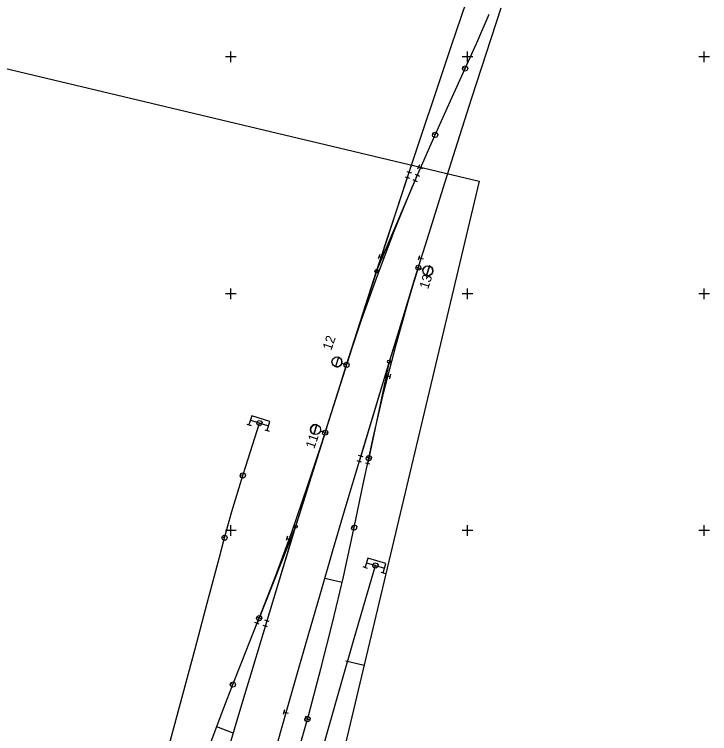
# Model space of a CAD drawing. Extents: x -733601 to -733291, y -1137892 to -1137187.
# Drawn here: x -733445.8 to -733298.9, y -1137492.9 to -1137341 of the extents above; entities that cross this region are included whole.
import ezdxf

# ---------------------------------------------------------------- set-up
doc = ezdxf.new("R2010")
doc.units = 0
for name, color, linetype in [('Krizky_Hektom_sit', 7, 'Continuous'), ('Rozvrzeni', 7, 'Continuous'), ('SIT_PUV_ZELEZNICE', 7, 'Continuous')]:
    doc.layers.add(name, color=color, linetype=linetype)

msp = doc.modelspace()

# ---------------------------------------------------------------- linework, layer by layer
at = {"layer": 'Krizky_Hektom_sit'}
for p, q in [((-733400, -1137351.13), (-733400, -1137348.87)), ((-733350, -1137351.13), (-733350, -1137348.87)), ((-733300, -1137351.13), (-733300, -1137348.87)), ((-733398.87, -1137350), (-733401.13, -1137350)), ((-733348.87, -1137350), (-733351.13, -1137350)), ((-733298.87, -1137350), (-733301.13, -1137350)), ((-733400, -1137401.13), (-733400, -1137398.87)), ((-733350, -1137401.13), (-733350, -1137398.87)), ((-733300, -1137401.13), (-733300, -1137398.87)), ((-733398.87, -1137400), (-733401.13, -1137400)), ((-733348.87, -1137400), (-733351.13, -1137400)), ((-733298.87, -1137400), (-733301.13, -1137400)), ((-733400, -1137451.13), (-733400, -1137448.87)), ((-733350, -1137451.13), (-733350, -1137448.87)), ((-733300, -1137451.13), (-733300, -1137448.87)), ((-733398.87, -1137450), (-733401.13, -1137450)), ((-733348.87, -1137450), (-733351.13, -1137450)), ((-733298.87, -1137450), (-733301.13, -1137450))]:
    msp.add_line(p, q, dxfattribs=at)
at = {"layer": 'Rozvrzeni'}
msp.add_line((-733375.74, -1137477.48), (-733371.85, -1137478.4), dxfattribs=at)
msp.add_lwpolyline([(-733564.93, -1137648.32), (-733492.01, -1137341.87), (-733347.54, -1137376.25), (-733420.47, -1137682.7)], close=True, dxfattribs=at)
at = {"layer": 'SIT_PUV_ZELEZNICE'}
for p, q in [((-733350.98, -1137352.24), (-733350.87, -1137352.01)), ((-733350.87, -1137352.01), (-733350.54, -1137351.88)), ((-733350.54, -1137351.88), (-733350.09, -1137352.09)), ((-733351.08, -1137352.46), (-733350.98, -1137352.24)), ((-733350.95, -1137352.79), (-733351.08, -1137352.46)), ((-733350.52, -1137352.44), (-733350.98, -1137352.24)), ((-733350.5, -1137353), (-733350.95, -1137352.79)), ((-733350.17, -1137352.88), (-733350.5, -1137353)), ((-733349.96, -1137352.42), (-733350.17, -1137352.88)), ((-733350.09, -1137352.09), (-733349.96, -1137352.42)), ((-733357.44, -1137366.49), (-733357.34, -1137366.26)), ((-733357.32, -1137366.82), (-733357.44, -1137366.49)), ((-733357.34, -1137366.26), (-733357.24, -1137366.03)), ((-733356.89, -1137366.47), (-733357.34, -1137366.26)), ((-733356.86, -1137367.03), (-733357.32, -1137366.82)), ((-733357.24, -1137366.03), (-733356.91, -1137365.91)), ((-733356.91, -1137365.91), (-733356.45, -1137366.12)), ((-733356.53, -1137366.9), (-733356.86, -1137367.03)), ((-733356.33, -1137366.45), (-733356.53, -1137366.9)), ((-733356.45, -1137366.12), (-733356.33, -1137366.45)), ((-733360.19, -1137372.76), (-733360.6, -1137373.67)), ((-733359.48, -1137373.62), (-733360.4, -1137373.21)), ((-733368.56, -1137391.68), (-733368.89, -1137392.62)), ((-733367.78, -1137392.48), (-733368.73, -1137392.15)), ((-733360.15, -1137391.96), (-733360.45, -1137392.91)), ((-733359.35, -1137392.73), (-733360.3, -1137392.44)), ((-733360.97, -1137394.58), (-733360.9, -1137394.35)), ((-733360.81, -1137394.9), (-733360.97, -1137394.58)), ((-733360.9, -1137394.35), (-733360.82, -1137394.11)), ((-733360.42, -1137394.49), (-733360.9, -1137394.35)), ((-733360.82, -1137394.11), (-733360.51, -1137393.94)), ((-733360.51, -1137393.94), (-733360.03, -1137394.09)), ((-733360.42, -1137394.49), (-733359.39, -1137394.83)), ((-733360.03, -1137394.09), (-733359.87, -1137394.4)), ((-733359.87, -1137394.4), (-733360.02, -1137394.88)), ((-733358.68, -1137396.15), (-733358.09, -1137394.14)), ((-733360.33, -1137395.05), (-733360.81, -1137394.9)), ((-733360.02, -1137394.88), (-733360.33, -1137395.05)), ((-733377.29, -1137413.38), (-733377.93, -1137415.39)), ((-733375.58, -1137415.02), (-733376.61, -1137414.7)), ((-733376.13, -1137415.11), (-733376.05, -1137414.87)), ((-733376.13, -1137415.11), (-733376.05, -1137414.87)), ((-733375.97, -1137415.42), (-733376.13, -1137415.11)), ((-733375.97, -1137415.42), (-733376.13, -1137415.11)), ((-733376.05, -1137414.87), (-733375.98, -1137414.63)), ((-733376.05, -1137414.87), (-733375.98, -1137414.63)), ((-733375.58, -1137415.02), (-733376.05, -1137414.87)), ((-733375.58, -1137415.02), (-733376.05, -1137414.87)), ((-733375.98, -1137414.63), (-733375.66, -1137414.47)), ((-733375.98, -1137414.63), (-733375.66, -1137414.47)), ((-733375.49, -1137415.57), (-733375.97, -1137415.42)), ((-733375.49, -1137415.57), (-733375.97, -1137415.42)), ((-733375.66, -1137414.47), (-733375.19, -1137414.62)), ((-733375.66, -1137414.47), (-733375.19, -1137414.62)), ((-733375.17, -1137415.41), (-733375.49, -1137415.57)), ((-733375.17, -1137415.41), (-733375.49, -1137415.57)), ((-733375.19, -1137414.62), (-733375.02, -1137414.93)), ((-733375.19, -1137414.62), (-733375.02, -1137414.93)), ((-733375.02, -1137414.93), (-733375.17, -1137415.41)), ((-733375.02, -1137414.93), (-733375.17, -1137415.41)), ((-733367.31, -1137417.23), (-733366.34, -1137417.46)), ((-733366.45, -1137417.95), (-733366.22, -1137416.97)), ((-733395.59, -1137425.75), (-733396.2, -1137427.66)), ((-733395.59, -1137425.75), (-733396.2, -1137427.66)), ((-733391.78, -1137426.96), (-733395.59, -1137425.75)), ((-733391.78, -1137426.96), (-733395.59, -1137425.75)), ((-733396.67, -1137427.51), (-733395.72, -1137427.81)), ((-733396.67, -1137427.51), (-733395.72, -1137427.81)), ((-733395.89, -1137426.7), (-733392.08, -1137427.91)), ((-733395.89, -1137426.7), (-733392.08, -1137427.91)), ((-733394.54, -1137427.4), (-733394.46, -1137427.16)), ((-733394.38, -1137427.71), (-733394.54, -1137427.4)), ((-733394.46, -1137427.16), (-733394.39, -1137426.92)), ((-733393.99, -1137427.31), (-733394.46, -1137427.16)), ((-733394.39, -1137426.92), (-733394.07, -1137426.76)), ((-733393.9, -1137427.86), (-733394.38, -1137427.71)), ((-733394.07, -1137426.76), (-733393.6, -1137426.91)), ((-733393.59, -1137427.7), (-733393.9, -1137427.86)), ((-733393.6, -1137426.91), (-733393.43, -1137427.22)), ((-733393.43, -1137427.22), (-733393.59, -1137427.7)), ((-733392.38, -1137428.87), (-733391.78, -1137426.96)), ((-733392.38, -1137428.87), (-733391.78, -1137426.96)), ((-733381.83, -1137427.68), (-733382.46, -1137429.68)), ((-733392.86, -1137428.72), (-733391.91, -1137429.02)), ((-733392.86, -1137428.72), (-733391.91, -1137429.02)), ((-733380.11, -1137429.32), (-733381.14, -1137428.99)), ((-733380.66, -1137429.41), (-733380.51, -1137428.93)), ((-733380.66, -1137429.41), (-733380.59, -1137429.17)), ((-733380.5, -1137429.72), (-733380.66, -1137429.41)), ((-733380.5, -1137429.72), (-733380.66, -1137429.41)), ((-733380.59, -1137429.17), (-733380.51, -1137428.93)), ((-733380.11, -1137429.32), (-733380.59, -1137429.17)), ((-733380.51, -1137428.93), (-733380.2, -1137428.77)), ((-733380.51, -1137428.93), (-733380.2, -1137428.77)), ((-733380.2, -1137428.77), (-733379.72, -1137428.92)), ((-733380.2, -1137428.77), (-733379.72, -1137428.92)), ((-733380.11, -1137429.32), (-733379.63, -1137429.47)), ((-733379.72, -1137428.92), (-733379.56, -1137429.23)), ((-733379.72, -1137428.92), (-733379.56, -1137429.23)), ((-733379.56, -1137429.23), (-733379.71, -1137429.71)), ((-733379.63, -1137429.47), (-733379.71, -1137429.71)), ((-733379.56, -1137429.23), (-733379.63, -1137429.47)), ((-733380.02, -1137429.87), (-733380.5, -1137429.72)), ((-733380.02, -1137429.87), (-733380.5, -1137429.72)), ((-733379.71, -1137429.71), (-733380.02, -1137429.87)), ((-733379.71, -1137429.71), (-733380.02, -1137429.87)), ((-733371.42, -1137434.85), (-733371.36, -1137434.6)), ((-733371.22, -1137435.14), (-733371.42, -1137434.85)), ((-733371.36, -1137434.6), (-733371.31, -1137434.36)), ((-733370.88, -1137434.71), (-733371.36, -1137434.6)), ((-733371.31, -1137434.36), (-733371.02, -1137434.17)), ((-733370.73, -1137435.25), (-733371.22, -1137435.14)), ((-733371.02, -1137434.17), (-733370.53, -1137434.27)), ((-733370.44, -1137435.05), (-733370.73, -1137435.25)), ((-733370.53, -1137434.27), (-733370.33, -1137434.56)), ((-733370.33, -1137434.56), (-733370.44, -1137435.05)), ((-733398.05, -1137438.46), (-733397.97, -1137438.22)), ((-733397.88, -1137438.77), (-733398.05, -1137438.46)), ((-733397.97, -1137438.22), (-733397.89, -1137437.98)), ((-733397.49, -1137438.37), (-733397.97, -1137438.22)), ((-733397.89, -1137437.98), (-733397.58, -1137437.82)), ((-733397.58, -1137437.82), (-733397.1, -1137437.97)), ((-733397.1, -1137437.97), (-733396.94, -1137438.28)), ((-733396.94, -1137438.28), (-733397.09, -1137438.76)), ((-733397.41, -1137438.92), (-733397.88, -1137438.77)), ((-733397.09, -1137438.76), (-733397.41, -1137438.92)), ((-733374.46, -1137449.28), (-733374.41, -1137449.04)), ((-733374.41, -1137449.04), (-733374.11, -1137448.84)), ((-733374.11, -1137448.84), (-733373.62, -1137448.95)), ((-733373.62, -1137448.95), (-733373.43, -1137449.24)), ((-733373.43, -1137449.24), (-733373.53, -1137449.73)), ((-733374.51, -1137449.53), (-733374.46, -1137449.28)), ((-733374.32, -1137449.82), (-733374.51, -1137449.53)), ((-733373.97, -1137449.38), (-733374.46, -1137449.28)), ((-733373.83, -1137449.92), (-733374.32, -1137449.82)), ((-733373.53, -1137449.73), (-733373.83, -1137449.92)), ((-733401.89, -1137451.66), (-733401.83, -1137451.42)), ((-733401.71, -1137451.97), (-733401.89, -1137451.66)), ((-733401.83, -1137451.42), (-733401.76, -1137451.18)), ((-733401.34, -1137451.55), (-733401.83, -1137451.42)), ((-733401.76, -1137451.18), (-733401.45, -1137451)), ((-733401.23, -1137452.1), (-733401.71, -1137451.97)), ((-733401.45, -1137451), (-733400.97, -1137451.13)), ((-733400.92, -1137451.92), (-733401.23, -1137452.1)), ((-733400.97, -1137451.13), (-733400.79, -1137451.44)), ((-733400.79, -1137451.44), (-733400.92, -1137451.92)), ((-733388.04, -1137451.18), (-733388.37, -1137452.13)), ((-733387.26, -1137451.98), (-733388.21, -1137451.65)), ((-733371.12, -1137455.85), (-733371.68, -1137457.76)), ((-733371.12, -1137455.85), (-733371.68, -1137457.76)), ((-733371.4, -1137456.8), (-733367.57, -1137457.94)), ((-733371.4, -1137456.8), (-733367.57, -1137457.94)), ((-733367.28, -1137456.98), (-733371.12, -1137455.85)), ((-733367.28, -1137456.98), (-733371.12, -1137455.85)), ((-733369.89, -1137456.99), (-733369.58, -1137456.82)), ((-733369.58, -1137456.82), (-733369.1, -1137456.96)), ((-733372.16, -1137457.62), (-733371.21, -1137457.91)), ((-733372.16, -1137457.62), (-733371.21, -1137457.91)), ((-733370.03, -1137457.47), (-733369.96, -1137457.23)), ((-733369.87, -1137457.78), (-733370.03, -1137457.47)), ((-733369.96, -1137457.23), (-733369.89, -1137456.99)), ((-733369.48, -1137457.37), (-733369.96, -1137457.23)), ((-733369.39, -1137457.92), (-733369.87, -1137457.78)), ((-733369.07, -1137457.76), (-733369.39, -1137457.92)), ((-733369.1, -1137456.96), (-733368.93, -1137457.28)), ((-733368.93, -1137457.28), (-733369.07, -1137457.76)), ((-733367.85, -1137458.9), (-733367.28, -1137456.98)), ((-733367.85, -1137458.9), (-733367.28, -1137456.98)), ((-733368.33, -1137458.76), (-733367.37, -1137459.04)), ((-733368.33, -1137458.76), (-733367.37, -1137459.04)), ((-733380.16, -1137460.02), (-733376.51, -1137460.88)), ((-733394.59, -1137468.53), (-733394.49, -1137468.3)), ((-733394.45, -1137468.86), (-733394.59, -1137468.53)), ((-733394.49, -1137468.3), (-733394.4, -1137468.07)), ((-733394.03, -1137468.48), (-733394.49, -1137468.3)), ((-733393.98, -1137469.04), (-733394.45, -1137468.86)), ((-733394.4, -1137468.07), (-733394.08, -1137467.93)), ((-733394.08, -1137467.93), (-733393.61, -1137468.11)), ((-733393.66, -1137468.9), (-733393.98, -1137469.04)), ((-733393.47, -1137468.44), (-733393.66, -1137468.9)), ((-733393.61, -1137468.11), (-733393.47, -1137468.44)), ((-733400.15, -1137482.54), (-733400.05, -1137482.31)), ((-733400.01, -1137482.86), (-733400.15, -1137482.54)), ((-733400.05, -1137482.31), (-733399.96, -1137482.07)), ((-733399.59, -1137482.49), (-733400.05, -1137482.31)), ((-733399.96, -1137482.07), (-733399.64, -1137481.93)), ((-733399.64, -1137481.93), (-733399.17, -1137482.12)), ((-733399.03, -1137482.44), (-733399.22, -1137482.91)), ((-733399.17, -1137482.12), (-733399.03, -1137482.44)), ((-733399.54, -1137483.05), (-733400.01, -1137482.86)), ((-733399.22, -1137482.91), (-733399.54, -1137483.05)), ((-733388.7, -1137487.88), (-733388.98, -1137488.84)), ((-733387.88, -1137488.64), (-733388.84, -1137488.36)), ((-733384.19, -1137489.2), (-733384.47, -1137490.16)), ((-733384.4, -1137489.93), (-733384.33, -1137489.69)), ((-733384.22, -1137490.24), (-733384.4, -1137489.93)), ((-733384.33, -1137489.69), (-733384.26, -1137489.45)), ((-733383.37, -1137489.96), (-733384.33, -1137489.68)), ((-733383.85, -1137489.82), (-733384.33, -1137489.69)), ((-733384.26, -1137489.45), (-733383.96, -1137489.27)), ((-733383.74, -1137490.37), (-733384.22, -1137490.24)), ((-733383.96, -1137489.27), (-733383.47, -1137489.41)), ((-733383.43, -1137490.2), (-733383.74, -1137490.37)), ((-733383.47, -1137489.41), (-733383.3, -1137489.71)), ((-733383.3, -1137489.71), (-733383.43, -1137490.2)), ((-733399.51, -1137492.76), (-733403.02, -1137491.43))]:
    msp.add_line(p, q, dxfattribs=at)
for points in [[(-733401.75, -1137500.31), (-733398.91, -1137490.72), (-733396.88, -1137483.92), (-733396.05, -1137481.14), (-733393.16, -1137471.57), (-733390.25, -1137462), (-733387.32, -1137452.44), (-733384.36, -1137442.89), (-733381.37, -1137433.34), (-733378.37, -1137423.81), (-733375.34, -1137414.28), (-733372.28, -1137404.75), (-733369.21, -1137395.24), (-733366.11, -1137385.73), (-733362.98, -1137376.23), (-733359.83, -1137366.74), (-733356.66, -1137357.26), (-733353.46, -1137347.78), (-733350.24, -1137338.32)], [(-733392.24, -1137502.27), (-733389.54, -1137492.65), (-733387.78, -1137486.44), (-733386.8, -1137483.03), (-733384.05, -1137473.42), (-733381.26, -1137463.81), (-733378.46, -1137454.21), (-733375.63, -1137444.62), (-733372.78, -1137435.04), (-733369.9, -1137425.46), (-733367, -1137415.89), (-733364.07, -1137406.33), (-733361.13, -1137396.77), (-733358.15, -1137387.22), (-733355.16, -1137377.68), (-733352.14, -1137368.15), (-733349.09, -1137358.63), (-733346.02, -1137349.11), (-733342.93, -1137339.6)], [(-733375.58, -1137415.02), (-733372.43, -1137405.53), (-733369.07, -1137396.11), (-733365.5, -1137386.77), (-733361.72, -1137377.51), (-733357.73, -1137368.34), (-733357.03, -1137366.79), (-733356.92, -1137366.55), (-733356.89, -1137366.47), (-733356.81, -1137366.31), (-733353.6, -1137359.23), (-733350.52, -1137352.44), (-733349.47, -1137350.12), (-733348.16, -1137347.17), (-733348.01, -1137346.84), (-733347.87, -1137346.51), (-733345.46, -1137340.96)], [(-733362.82, -1137374.16), (-733361.87, -1137374.48)], [(-733362.72, -1137375.46), (-733362.41, -1137374.51), (-733362.35, -1137374.32)], [(-733361.1, -1137374.77), (-733360.18, -1137375.16)], [(-733375.58, -1137415.02), (-733369.25, -1137395.21), (-733362.72, -1137375.46)], [(-733369.25, -1137395.21), (-733361.11, -1137376.07)], [(-733363.2, -1137375.3), (-733362.25, -1137375.62)], [(-733361.57, -1137375.88), (-733360.65, -1137376.27)], [(-733361.11, -1137376.07), (-733360.71, -1137375.15), (-733360.64, -1137374.97)], [(-733386.27, -1137498.5), (-733383.85, -1137489.82), (-733383.58, -1137488.87), (-733380.99, -1137479.21), (-733378.54, -1137469.51), (-733376.25, -1137459.78), (-733374.1, -1137450.01), (-733373.97, -1137449.38), (-733372.04, -1137440.23), (-733370.88, -1137434.71), (-733369.96, -1137430.45), (-733367.69, -1137420.71), (-733365.2, -1137411.02), (-733362.5, -1137401.39), (-733360.42, -1137394.49)], [(-733360.42, -1137394.49), (-733366.59, -1137414.36), (-733372.55, -1137434.28)], [(-733358.09, -1137394.14), (-733358.68, -1137396.15)], [(-733377.29, -1137413.38), (-733377.93, -1137415.39)], [(-733380.11, -1137429.32), (-733377.37, -1137420.65), (-733375.58, -1137415.02)], [(-733366.59, -1137414.36), (-733370.87, -1137434.71)], [(-733432.61, -1137592.18), (-733430.24, -1137582.46), (-733428.19, -1137572.68), (-733426.48, -1137562.82), (-733425.1, -1137553.05), (-733425.09, -1137552.92), (-733424.53, -1137548.39), (-733423.8, -1137543), (-733422.2, -1137533.13), (-733420.24, -1137523.33), (-733417.92, -1137513.6), (-733417.28, -1137511.16), (-733415.35, -1137503.94), (-733412.77, -1137494.28), (-733410.18, -1137484.62), (-733407.6, -1137474.96), (-733405.02, -1137465.3), (-733402.43, -1137455.64), (-733401.34, -1137451.55), (-733399.8, -1137445.99), (-733397.49, -1137438.37), (-733396.88, -1137436.43), (-733393.99, -1137427.31)], [(-733382.46, -1137429.68), (-733381.83, -1137427.68)], [(-733424.19, -1137560.03), (-733423.14, -1137555.99), (-733422.64, -1137554.1), (-733420.03, -1137544.45), (-733419.6, -1137542.91), (-733417.3, -1137534.83), (-733414.46, -1137525.24), (-733413.69, -1137522.71), (-733413.65, -1137522.55), (-733411.49, -1137515.69), (-733408.35, -1137506.2), (-733407.14, -1137502.71), (-733405.02, -1137496.77), (-733401.51, -1137487.4), (-733399.59, -1137482.49), (-733397.85, -1137478.1), (-733394.16, -1137468.81), (-733394.03, -1137468.48), (-733390.54, -1137459.48), (-733387.09, -1137450.1), (-733383.81, -1137440.65), (-733380.69, -1137431.15), (-733380.11, -1137429.32)], [(-733380.11, -1137429.32), (-733386.36, -1137449.15), (-733392.4, -1137469.05)], [(-733372.41, -1137435.57), (-733373.37, -1137435.29)], [(-733372.07, -1137434.42), (-733373.03, -1137434.14)], [(-733372.55, -1137434.28), (-733372.84, -1137435.24), (-733372.89, -1137435.43)], [(-733370.39, -1137434.81), (-733371.36, -1137434.6)], [(-733370.87, -1137434.71), (-733371.08, -1137435.68), (-733371.12, -1137435.88)], [(-733370.63, -1137435.98), (-733371.61, -1137435.78)], [(-733386.36, -1137449.15), (-733394.03, -1137468.48)], [(-733381.59, -1137499.49), (-733379.48, -1137492), (-733376.74, -1137482.38), (-733373.97, -1137472.77), (-733371.18, -1137463.17), (-733369.48, -1137457.37)], [(-733393.57, -1137468.67), (-733394.49, -1137468.3)], [(-733394.03, -1137468.48), (-733394.4, -1137469.41), (-733394.47, -1137469.6)], [(-733391.92, -1137469.2), (-733392.88, -1137468.91)], [(-733394.01, -1137469.78), (-733394.94, -1137469.41)], [(-733392.27, -1137470.35), (-733393.23, -1137470.06)], [(-733392.4, -1137469.05), (-733392.69, -1137470.01), (-733392.75, -1137470.2)]]:
    msp.add_lwpolyline(points, dxfattribs=at)
for centre, radius in [((-733358.39, -1137395.14), 1.05), ((-733369.25, -1137395.21), 0.35), ((-733377.61, -1137414.38), 1.05), ((-733366.59, -1137414.36), 0.35), ((-733382.14, -1137428.68), 1.05), ((-733386.36, -1137449.15), 0.35)]:
    msp.add_circle(centre, radius, dxfattribs=at)
for centre, start, end in [((-733358.39, -1137395.14), 0, 73.5871), ((-733358.39, -1137395.14), 253.5871, 0), ((-733377.61, -1137414.38), 0, 72.3619), ((-733377.61, -1137414.38), 252.3619, 0), ((-733382.14, -1137428.68), 72.3619, 180), ((-733382.14, -1137428.68), 180, 252.3619)]:
    msp.add_arc(centre, 1.05, start, end, dxfattribs=at)

# ---------------------------------------------------------------- texts
for s, rotation, p in [('13', 72.0468, (-733358.36, -1137399.16)), ('12', 70.9323, (-733378.82, -1137412.07)), ('11', 70.9323, (-733382.41, -1137432.86))]:
    msp.add_text(s, height=2, rotation=rotation, dxfattribs=at).set_placement(p)

doc.saveas('drawing.dxf')
